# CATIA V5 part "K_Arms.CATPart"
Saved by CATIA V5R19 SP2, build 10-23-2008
Part number: Arms
Bounding box of the stored display mesh (mm): x 0 to 2, y -3.5 to 3.5, z -3.49 to 33.49
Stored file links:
  G:\Khaled_CFAO_2011\ST2M\ST2M_GR1\bgaltie\bgaltie\Khaled\CAD_thinkMOTION\K_Arms.CATPart
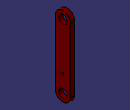
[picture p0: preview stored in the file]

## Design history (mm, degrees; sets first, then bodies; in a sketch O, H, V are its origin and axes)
AxisSystem1: origin (0, 0, 0), X (1, 0, 0), Y (0, 1, 0), Z (0, 0, 1)
Body1 (main body)
  Sketch1 on YZ plane of AxisSystem1, origin (0, 0, 0), H (0, 1, 0), V (0, 0, 1)
    construction line L1 (0, 0) -> (0, 30)
    point P1 (0, 0)
    point P2 (0, 30)
    line L2 (-3.5, 0) -> (-3.5, 30)
    line L3 (3.5, 30) -> (3.5, 0)
    arc A1 centre (0, 30) radius 3.5 from (-3.5, 30) to (3.5, 30) cw
    arc A2 centre (0, 0) radius 3.5 from (3.5, 0) to (-3.5, 0) cw
    circle A3 centre (0, 30) radius 2
    point P7 (0, 30)
    point P8 (0, 0)
    circle A4 centre (0, 0) radius 2
    distance L1 L2 = 3.5
    length L1 = 30
    radius A3 = 2
    vertical: L1 V
    tangency: A1 L2, A2 L2, A1 L3, A2 L3
    coincidence: P1 O, P8 O, P7 P2
  Pad1: profile Sketch1, direction (1, 0, 0), length 2
  Sketch2 on end face of Pad1, origin (2, -1.3989, 12.0062), H (0, 1, 0), V (0, 0, 1)
    point P1 (1.3989, -4.0062)
    reference projected point E1 (1.3989, -12.0062) from vertex [YZ plane of AxisSystem1 | ZX plane of AxisSystem1 | XY plane of AxisSystem1]
    reference projected line E2 (-2.1011, 17.9938) -> (-2.1011, -12.0062) from edge [face of Pad1 from Sketch1.L2 | end face of Pad1]
    distance P1 E1 = 8
    distance P1 E2 = 3.5
  Hole1: placed by Sketch2, at (2, 0, 8) direction (-1, 0, 0), diameter 1, depth 1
